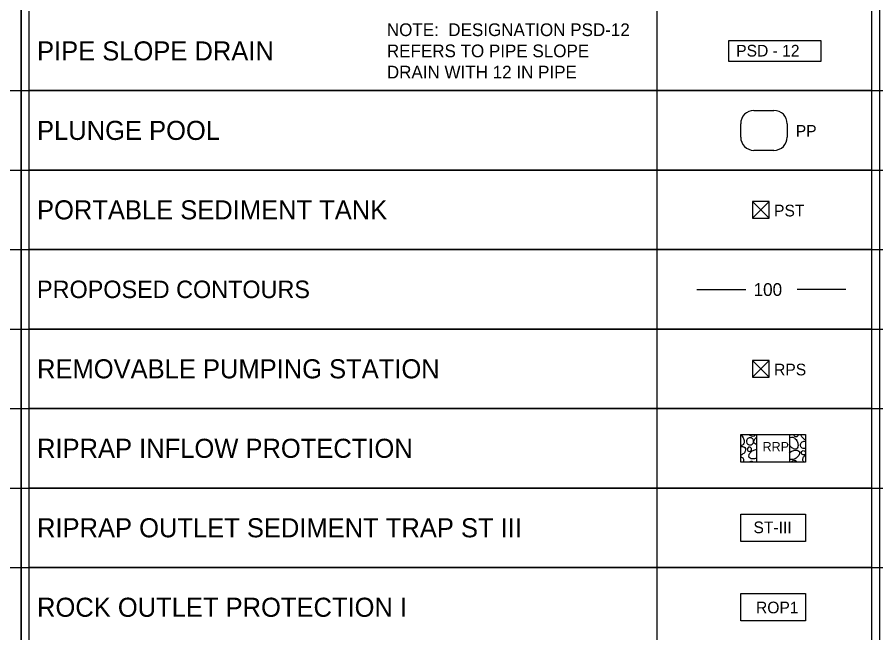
# Model space of a CAD drawing. Extents: x 1.3 to 34, y 0 to 22.5.
# Drawn here: x 7.38 to 12.78, y 11.41 to 15.29 of the extents above; entities that cross this region are included whole.
import ezdxf

# ---------------------------------------------------------------- set-up
doc = ezdxf.new("R2010")
doc.units = 0
for name, color, linetype in [('ANNO-SYMB', 7, 'Continuous'), ('ANNO-TABL', 7, 'Continuous'), ('USER-LINE', 7, 'Continuous')]:
    doc.layers.add(name, color=color, linetype=linetype)

msp = doc.modelspace()

# ---------------------------------------------------------------- linework, layer by layer
at = {"layer": 'ANNO-SYMB'}
for p, q in [((12, 14.0228), (12.1044, 14.1272)), ((12, 14.1272), (12.1044, 14.0228)), ((11.65, 13.575), (11.9579, 13.575)), ((12.5872, 13.575), (12.2793, 13.575)), ((12, 13.0228), (12.1044, 13.1272)), ((12, 13.1272), (12.1044, 13.0228)), ((12.0238, 12.6613), (12.0238, 12.4887)), ((12.2312, 12.6613), (12.2312, 12.4887)), ((12.2376, 12.6613), (12.2312, 12.656))]:
    msp.add_line(p, q, dxfattribs=at)
for points in [[(11.85, 15.1407), (12.4294, 15.1407), (12.4294, 15.0093), (11.85, 15.0093)], [(12, 14.0228), (12.1044, 14.0228), (12.1044, 14.1272), (12, 14.1272)], [(12, 13.0228), (12.1044, 13.0228), (12.1044, 13.1272), (12, 13.1272)], [(11.925, 12.6613), (12.3333, 12.6613), (12.3333, 12.4887), (11.925, 12.4887)], [(11.925, 12.1613), (12.3333, 12.1613), (12.3333, 11.9887), (11.925, 11.9887)], [(11.925, 11.6613), (12.3333, 11.6613), (12.3333, 11.4887), (11.925, 11.4887)]]:
    msp.add_lwpolyline(points, close=True, dxfattribs=at)
for points in [[(12.0087, 14.7006), (12.1343, 14.7006)], [(11.925, 14.5331), (11.925, 14.6169)], [(12.218, 14.6169), (12.218, 14.5331)], [(12.1343, 14.4494), (12.0087, 14.4494)]]:
    msp.add_lwpolyline(points, dxfattribs=at)
for centre, start, end in [((12.0087, 14.6169), 90, 180), ((12.1343, 14.6169), 0, 90), ((12.0087, 14.5331), 180, 270), ((12.1343, 14.5331), 270, 0)]:
    msp.add_arc(centre, 0.0837, start, end, dxfattribs=at)
for points in [[(11.9373, 12.6472), (11.9461, 12.6245), (11.9446, 12.6047), (11.9358, 12.5944), (11.925, 12.593)], [(11.9253, 12.6613), (11.9292, 12.6575), (11.938, 12.6458)], [(11.9615, 12.6223), (11.9733, 12.6392), (11.9924, 12.6399), (12.0056, 12.6267), (12.0034, 12.6076), (11.9916, 12.5973), (11.9733, 12.5988), (11.9645, 12.6076), (11.9615, 12.6223)], [(12.0184, 12.6613), (12.0181, 12.6605), (12.0093, 12.6509), (11.9924, 12.6509), (11.9778, 12.6613)], [(12.0238, 12.5986), (12.0232, 12.5988), (12.0107, 12.6076), (12.01, 12.6245), (12.0195, 12.6399), (12.0238, 12.6433)], [(12.2312, 12.6386), (12.2362, 12.6431), (12.2531, 12.6446), (12.2685, 12.635), (12.2773, 12.6233)], [(12.2862, 12.6613), (12.2839, 12.6534), (12.2773, 12.6475), (12.2663, 12.6482), (12.2604, 12.6534), (12.2591, 12.6613)], [(12.3333, 12.6277), (12.3317, 12.6284), (12.3133, 12.6431), (12.3031, 12.6613)], [(11.925, 12.5856), (11.9454, 12.5834), (11.9549, 12.5745), (11.9542, 12.5577), (11.9395, 12.5393), (11.925, 12.5306)], [(11.9667, 12.5709), (11.974, 12.5812), (11.985, 12.5819), (11.9931, 12.5738), (11.9924, 12.5621), (11.985, 12.5562), (11.974, 12.5577), (11.9689, 12.5628), (11.9667, 12.5709)], [(12.2766, 12.6247), (12.2854, 12.602), (12.2839, 12.5821), (12.2751, 12.5719), (12.2582, 12.5726), (12.2391, 12.5873), (12.2312, 12.6011)], [(12.3008, 12.5998), (12.3126, 12.6167), (12.3317, 12.6174), (12.3333, 12.6164)], [(12.3333, 12.576), (12.3309, 12.5748), (12.3126, 12.5763), (12.3038, 12.5851), (12.3008, 12.5998)], [(12.0238, 12.5137), (12.0122, 12.5092), (11.9909, 12.5092), (11.9784, 12.5173), (11.9777, 12.5349), (11.9872, 12.5496), (11.9982, 12.5591)], [(11.9975, 12.5584), (12.0195, 12.5672), (12.0238, 12.5683)], [(12.2421, 12.5542), (12.2641, 12.563), (12.2847, 12.5608), (12.2942, 12.552), (12.2935, 12.5351), (12.2788, 12.5168), (12.256, 12.505), (12.2347, 12.505), (12.2312, 12.5063)], [(12.2312, 12.5449), (12.2318, 12.5454), (12.2428, 12.5542)], [(12.306, 12.5484), (12.3133, 12.5586), (12.3243, 12.5594), (12.3324, 12.5513), (12.3333, 12.549)], [(12.3333, 12.5431), (12.3317, 12.5395), (12.3243, 12.5337), (12.3133, 12.5351), (12.3082, 12.5403), (12.306, 12.5484)], [(12.3249, 12.4887), (12.3177, 12.4947), (12.317, 12.5124), (12.3265, 12.5271), (12.3333, 12.5329)], [(11.925, 12.5221), (11.9299, 12.5202), (11.9432, 12.5062), (11.942, 12.4887)], [(11.9804, 12.4887), (11.9813, 12.4901), (12.0004, 12.4916), (12.0046, 12.4887)], [(12.2449, 12.4887), (12.2502, 12.4962), (12.2693, 12.4977), (12.2795, 12.4887)]]:
    msp.add_spline(points, degree=3, dxfattribs=at)
at = {"layer": 'ANNO-TABL'}
for p, q in [((2, 14.825), (18.2, 14.825)), ((2, 14.325), (18.2, 14.325)), ((2, 13.825), (18.2, 13.825)), ((2, 13.325), (18.2, 13.325)), ((2, 12.825), (18.2, 12.825)), ((2, 12.325), (18.2, 12.325)), ((2, 11.825), (18.2, 11.825))]:
    msp.add_line(p, q, dxfattribs=at)
for points in [[(2, 7.825), (7.4, 7.825), (7.4, 19.825), (2, 19.825)], [(7.4, 7.825), (12.8, 7.825), (12.8, 19.825), (7.4, 19.825)]]:
    msp.add_lwpolyline(points, close=True, dxfattribs=at)
at = {"layer": 'USER-LINE'}
for p, q in [((7.45, 14.825), (7.45, 15.325)), ((11.4, 14.825), (11.4, 15.325)), ((12.75, 14.825), (12.75, 15.325)), ((7.45, 14.325), (7.45, 14.825)), ((11.4, 14.825), (7.45, 14.825)), ((12.75, 14.825), (11.4, 14.825)), ((11.4, 14.325), (11.4, 14.825)), ((12.75, 14.325), (12.75, 14.825)), ((7.45, 13.825), (7.45, 14.325)), ((11.4, 14.325), (7.45, 14.325)), ((12.75, 14.325), (11.4, 14.325)), ((11.4, 13.825), (11.4, 14.325)), ((12.75, 13.825), (12.75, 14.325)), ((7.45, 13.325), (7.45, 13.825)), ((11.4, 13.825), (7.45, 13.825)), ((12.75, 13.825), (11.4, 13.825)), ((11.4, 13.325), (11.4, 13.825)), ((12.75, 13.325), (12.75, 13.825)), ((7.45, 12.825), (7.45, 13.325)), ((11.4, 13.325), (7.45, 13.325)), ((12.75, 13.325), (11.4, 13.325)), ((11.4, 12.825), (11.4, 13.325)), ((12.75, 12.825), (12.75, 13.325)), ((7.45, 12.325), (7.45, 12.825)), ((11.4, 12.825), (7.45, 12.825)), ((12.75, 12.825), (11.4, 12.825)), ((11.4, 12.325), (11.4, 12.825)), ((12.75, 12.325), (12.75, 12.825)), ((7.45, 11.825), (7.45, 12.325)), ((11.4, 12.325), (7.45, 12.325)), ((12.75, 12.325), (11.4, 12.325)), ((11.4, 11.825), (11.4, 12.325)), ((12.75, 11.825), (12.75, 12.325)), ((7.45, 11.325), (7.45, 11.825)), ((11.4, 11.825), (7.45, 11.825)), ((12.75, 11.825), (11.4, 11.825)), ((11.4, 11.325), (11.4, 11.825)), ((12.75, 11.325), (12.75, 11.825))]:
    msp.add_line(p, q, dxfattribs=at)

# ---------------------------------------------------------------- texts
at = {"layer": 'ANNO-SYMB'}
for s, height, p in [('PSD - 12', 0.07344, (11.8969, 15.0397)), ('PP', 0.07344, (12.2716, 14.5351)), ('PST', 0.07344, (12.1351, 14.0338)), ('100', 0.08035, (12.0063, 13.5335)), ('RPS', 0.07344, (12.1351, 13.0338)), ('RRP', 0.05875, (12.063, 12.5556)), ('ST-III', 0.07344, (12.0055, 12.0409)), ('ROP1', 0.07344, (12.0215, 11.5368))]:
    msp.add_text(s, height=height, dxfattribs=at).set_placement(p)
at = {"layer": 'ANNO-TABL'}
for s, height, p in [('NOTE:  DESIGNATION PSD-12', 0.08, (9.7, 15.1683)), ('PIPE SLOPE DRAIN', 0.12, (7.5, 15.015)), ('REFERS TO PIPE SLOPE', 0.08, (9.7, 15.035)), ('DRAIN WITH 12 IN PIPE', 0.08, (9.7, 14.9017)), ('PLUNGE POOL', 0.12, (7.5, 14.515)), ('PORTABLE SEDIMENT TANK', 0.12, (7.5, 14.015)), ('PROPOSED CONTOURS', 0.11, (7.5, 13.52)), ('REMOVABLE PUMPING STATION', 0.12, (7.5, 13.015)), ('RIPRAP INFLOW PROTECTION', 0.12, (7.5, 12.515)), ('RIPRAP OUTLET SEDIMENT TRAP ST III', 0.12, (7.5, 12.015)), ('ROCK OUTLET PROTECTION I', 0.12, (7.5, 11.515))]:
    msp.add_text(s, height=height, dxfattribs=at).set_placement(p)

doc.saveas('drawing.dxf')
